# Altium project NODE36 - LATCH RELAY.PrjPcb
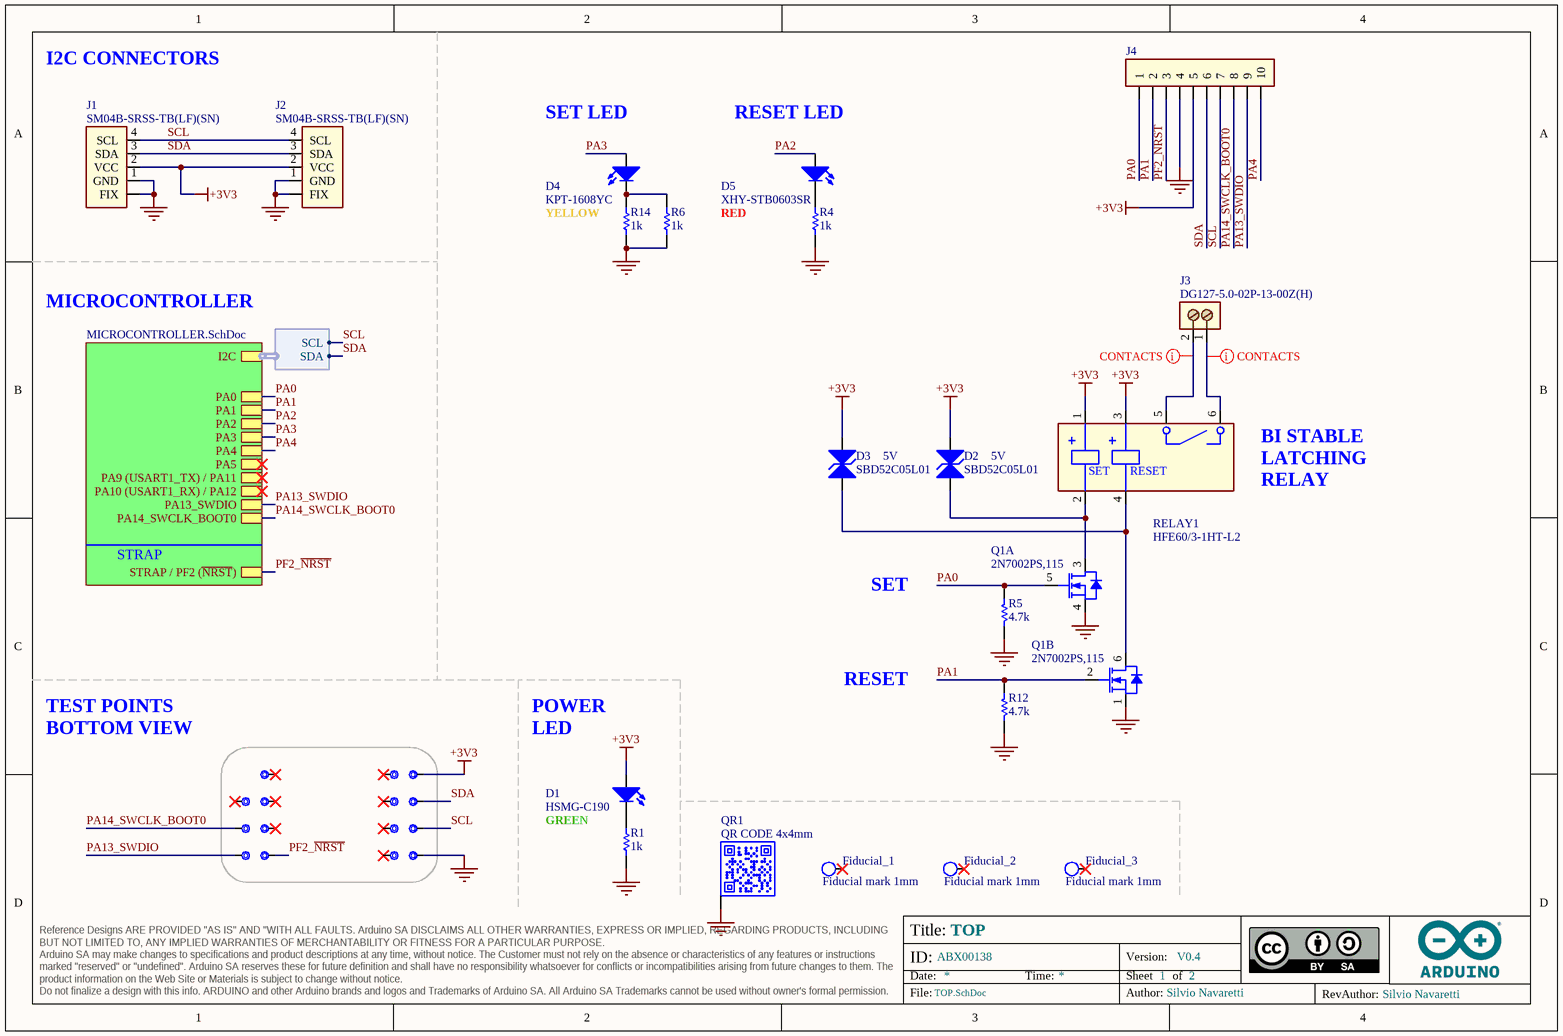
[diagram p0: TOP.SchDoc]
ASSEMBLY_BGA: _; ASSEMBLY_PRESSFIT: _; ASSEMBLY_SMD: X; ASSEMBLY_THT: _; BOARD_CODENAME: NODE36 LATCH RELAY; BOARD_INFO_AUTHOR: Silvio Navaretti; BOARD_INFO_AUTHOR_REV: Silvio Navaretti; BOARD_INFO_Er: _; BOARD_INFO_FLEX: _; BOARD_INFO_FR4: X; BOARD_INFO_FR4_HTG: _; BOARD_INFO_IPC1: _; BOARD_INFO_IPC2: X; BOARD_INFO_IPC3: _; BOARD_INFO_IPC_NA: _; BOARD_INFO_NUMBER_OF_LAYERS: 2; BOARD_INFO_PCB_SIZE: 41.00x25.36mm; BOARD_INFO_POLYMIDE: _; BOARD_INFO_RIGID: X; BOARD_INFO_RIGID/FLEX: _; BOARD_INFO_TBD: _; BOARD_INFO_THICKNESS: 1.6mm; DRILLS_BLIND: _; DRILLS_BURIED: _; DRILLS_COPPER_FILLING: _; DRILLS_FULL: X; DRILLS_LASER: _; DRILLS_PRESSFIT: _; DRILLS_RESIN_FILLING: _; DRILLS_SLOT: _; DRILLS_SOLDER_FILLING: X; FINISH_ADJUSTMENTS: _; FINISH_EDGE_PLATING: _; FINISH_ENIG: _; FINISH_HAL: _; FINISH_HAL_LF: X; FINISH_NI/AU: _; FINISH_SILK_BOTTOM: X; FINISH_SILK_COLOR: WHITE; FINISH_SILK_TOP: X; FINISH_SN/PB: _; FINISH_SOLDERMASK_BOTTOM: X; FINISH_SOLDERMASK_COLOR: BLUE; FINISH_SOLDERMASK_PEELABLE_BOTTOM: _; FINISH_SOLDERMASK_PEELABLE_COLOR: _; FINISH_SOLDERMASK_PEELABLE_TOP: _; FINISH_SOLDERMASK_TOP: X; FINISH_TABS: _; FINISH_TBD: _; INSULATION_MIN_INNER: 0.15mm; INSULATION_MIN_OUTER: 0.15mm; PANEL_MILLING: X; PANEL_NOT_REQUESTED: _; PANEL_NUMBER_OF_FIGURES: 30; PANEL_PROVIDED: X; PANEL_REQUESTED: _; PANEL_SCORING: X; PANEL_SIZE: 262.00x221.00mm; PANEL_TABS: _; SKU: ABX00138; TRACK_MIN_WIDTH_INNER: 0.15mm; TRACK_MIN_WIDTH_OUTER: 0.15mm; Version: V0.4; VIA_1: _; VIA_1_HOLE_MM: _; VIA_1_PAD_MM: _; VIA_2: _; VIA_2_HOLE_MM: _; VIA_2_PAD_MM: _; VIA_3: _; VIA_3_HOLE_MM: _; VIA_3_PAD_MM: _; VIA_4: _; VIA_4_HOLE_MM: _; VIA_4_PAD_MM: _; VIA_5: _; VIA_5_HOLE_MM: _; VIA_5_PAD_MM: _; VIA_THROUGH: X; VIA_THROUGH_HOLE_MM: 0.3; VIA_THROUGH_PAD_MM: 0.6
2 sheets, 43 parts. Net scope: hierarchical (ports join the sheet entries above them; power ports are global).
Board files: PCB.PcbDoc, PANEL.PcbDoc
Sheets:
  TOP.SchDoc
    U_MICROCONTROLLER = MICROCONTROLLER.SchDoc

## Sheet TOP.SchDoc: TOP
size A4; Revision: V0.4; SheetNumber: 1; SheetTotal: 2

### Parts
3V3  Test point 1.00mm  [TP-1.00MM]  (value not drawn)  (no BOM)
D1  HSMG-C190  [LEDC1608X80N-AK]
D2  SBD52C05L01  Voltage Rating (DC): 5V  [SOD523 NO POLARITY]
D3  SBD52C05L01  Voltage Rating (DC): 5V  [SOD523 NO POLARITY]
D4  KPT-1608YC  [LEDC1608X80N-AK]
D5  XHY-STB0603SR  [LEDC1608X80N-AK]
Fiducial_1  Fiducial mark 1mm  [Fiducial mark 1mm-Footprint-1]  (no BOM)
Fiducial_2  Fiducial mark 1mm  [Fiducial mark 1mm-Footprint-1]  (no BOM)
Fiducial_3  Fiducial mark 1mm  [Fiducial mark 1mm-Footprint-1]  (no BOM)
GND  Test point 1.00mm  [TP-1.00MM]  (value not drawn)  (no BOM)
J1  SM04B-SRSS-TB(LF)(SN)  [SM04B-SRSS-TB(LF)(SN)-Footprint-1]
J2  SM04B-SRSS-TB(LF)(SN)  [SM04B-SRSS-TB(LF)(SN)-Footprint-1]
J3  DG127-5.0-02P-13-00Z(H)  [DG127-5.0-02P-14-00A(H)]
J4  HEADER TH 2.54mm VERT. 1x010POS  [PIN HEADER 2.54mm VERT. 1x10POS]  (value not drawn)  (no BOM)
NRST  Test point 1.00mm  [TP-1.00MM]  (value not drawn)  (no BOM)
PA6  Test point 1.00mm  [TP-1.00MM]  (value not drawn)  (no BOM)
PA7  Test point 1.00mm  [TP-1.00MM]  (value not drawn)  (no BOM)
PC14  Test point 1.00mm  [TP-1.00MM]  (value not drawn)  (no BOM)
PC15  Test point 1.00mm  [TP-1.00MM]  (value not drawn)  (no BOM)
Q1  2N7002PS,115  [SOT363]  (parts A,B of 2)
QR1  QR CODE 4x4mm  [QR CODE 4x4mm]  (no BOM)
R1  value 1k  [RES-0402]  (hidden comment: CRCW04021K00FKEDC)
R4  value 1k  [RES-0402]  (hidden comment: CRCW04021K00FKEDC)
R5  value 4.7k  [RES-0402]  (hidden comment: RC0402FR-074K7L)
R6  value 1k  [RES-0402]  (hidden comment: CRCW04021K00FKEDC)
R12  value 4.7k  [RES-0402]  (hidden comment: RC0402FR-074K7L)
R14  value 1k  [RES-0402]  (hidden comment: CRCW04021K00FKEDC)
RELAY1  HFE60/3-1HT-L2  [HFE60/3-1HT-L2]
SCL  Test point 1.00mm  [TP-1.00MM]  (value not drawn)  (no BOM)
SDA  Test point 1.00mm  [TP-1.00MM]  (value not drawn)  (no BOM)
SWCLK  Test point 1.00mm  [TP-1.00MM]  (value not drawn)  (no BOM)
SWDIO  Test point 1.00mm  [TP-1.00MM]  (value not drawn)  (no BOM)
TP9  Test point 1.00mm  [TP-1.00MM]  (value not drawn)  (no BOM)
TP10  Test point 1.00mm  [TP-1.00MM]  (value not drawn)  (no BOM)
TP11  Test point 1.00mm  [TP-1.00MM]  (value not drawn)  (no BOM)
TP12  Test point 1.00mm  [TP-1.00MM]  (value not drawn)  (no BOM)

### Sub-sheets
U_MICROCONTROLLER = MICROCONTROLLER.SchDoc: I2C (harness I2C), PA0, PA1, PA2, PA3, PA4, PA5, PA13_SWDIO, PA14_SWCLK_BOOT0, PA9 (USART1_TX) / PA11, PA10 (USART1_RX) / PA12, STRAP / PF2 (~{NRST})

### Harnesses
I2C: SDA, SCL

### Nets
+3V3: 3V3.X D1.A D2.2(A2) D3.2(A2) J1.2(VCC) J2.2(VCC) J4.5 RELAY1.1 RELAY1.3
GND: GND.X J1.1(GND) J1.FIX J2.1(GND) J2.FIX J4.4 Q1.1(S) Q1.4(S) QR1.PAD R1.1 R4.1 R5.2 R6.1 R12.2 R14.1
PA0: J4.1 Q1.5(G) R5.1 ; sheet U_MICROCONTROLLER/PA0
PA1: J4.2 Q1.2(G) R12.1 ; sheet U_MICROCONTROLLER/PA1
PA2: D5.A ; sheet U_MICROCONTROLLER/PA2
PA3: D4.A ; sheet U_MICROCONTROLLER/PA3
PA4: J4.10 ; sheet U_MICROCONTROLLER/PA4
PA13_SWDIO: J4.9 SWCLK.X ; sheet U_MICROCONTROLLER/PA13_SWDIO
PA14_SWCLK_BOOT0: J4.8 SWDIO.X ; sheet U_MICROCONTROLLER/PA14_SWCLK_BOOT0
PF2_~{NRST}: J4.3 NRST.X ; sheet U_MICROCONTROLLER/STRAP / PF2 (~{NRST})
SCL: J1.4(SCL) J2.4(SCL) J4.7 SCL.X ; sheet U_MICROCONTROLLER/I2C.SCL
SDA: J1.3(SDA) J2.3(SDA) J4.6 SDA.X ; sheet U_MICROCONTROLLER/I2C.SDA
NetD1_C: D1.C R1.2
NetD2_1: D2.1(A1) Q1.3(D) RELAY1.2
NetD3_1: D3.1(A1) Q1.6(D) RELAY1.4
NetD4_C: D4.C R6.2 R14.2
NetD5_C: D5.C R4.2
NetJ3_1: J3.1 RELAY1.6
NetJ3_2: J3.2 RELAY1.5

Not connected (* = marked no-connect by the designer): Fiducial_1 1*; Fiducial_2 1*; Fiducial_3 1*; PA6 X*; PA7 X*; PC14 X*; PC15 X*; TP9 X*; TP10 X*; TP11 X*; TP12 X*

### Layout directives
net class CONTACTS: NetJ3_1, NetJ3_2

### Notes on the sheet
- I2C CONNECTORS
- (near D4) SET LED
- (near D5) RESET LED
- YELLOW
- RED
- MICROCONTROLLER
- (near RELAY1) BI STABLE LATCHING RELAY
- STRAP
- SET
- RESET
- TEST POINTS BOTTOM VIEW
- (near D1) POWER LED
- GREEN

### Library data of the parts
3V3 GND NRST PA6 PA7 PC14 PC15 SCL SDA SWCLK SWDIO TP9-TP12 = UT0013-A.6: Manufacturer: This is not a component
D1 = L0009-A.5: LED SMD 0603 GREEN/568 15mcd 120^; Manufacturer: Broadcom; Code Arduino: 2204
D2 D3 = D0084-A.2: TVS BIDIRECTIONAL SMD Vr 5V, Vbr min 5.6V, 150W, SOD523; Manufacturer: YAGEO; Code Arduino: D0084
D4 = L0008-A.5: LED SMD 0603 GIA588   8mcd 120^; Manufacturer: Kingbright; Code Arduino: 2243
D5 = L0024-A.4: LED SMD 0603 RED 625nm, water clear, 42 to 88 mcd, 120 degrees, 1.6x0.8x0.6mm; Manufacturer: Shenzen Corehy Technology; Code Arduino: L0024
Fiducial_1-Fiducial_3 = UT0023-A.7: Fiducial mark 1mm clearance 2mm
J1 J2 = J0005-A.2: CONN JST 4POS SIDE 1MM TIN QWIIC; Code Arduino: J0005
J3 = J0519-A.6: CONN SCREW TERMINAL 2 POS pitch 5mm height 13.6mm BLACK; Manufacturer: Degson; Code Arduino: J0519
J4 = J0169-A.9: Code Arduino: J0169
Q1 = T0011-A.11: MOSFET 2N-CH 60V 0.32A SOT363; Manufacturer: Nexperia; Device Type: Mosfet 2N-CH SMD; Code Arduino: A5500
QR1 = QR-0001-A.5: QR CODE 4x4mm on layer 34 (This is not a component); Code Arduino: QRCODE_4x4mm
R1 R4 R6 R14 = R0007-A.24: RES CHIP 0402 1k 1% 1/16W; Manufacturer: Vishay; Code Arduino: 0140; Power: 62.5mW; Temperature coefficient: 100ppm
R5 R12 = R0013-A.24: RES CHIP 0402 4k7 1% 1/16W; Manufacturer: YAGEO; Power: 62.5mW; Code Arduino: 2196; Temperature coefficient: 200ppm
RELAY1 = S0067-A.7: Relay Bistable Latching Relay, SPST, 250VAC 5A (cos phi 1) 1250VA, 30VDC 5A 150W, Dual coil 30R 3V, 20.2x11.3x10.5mm; Manufacturer: Hongfa Relay; Code Arduino: S0067

## Sheet MICROCONTROLLER.SchDoc: MICROCONTROLLER
size A4; SheetNumber: 2; SheetTotal: 2
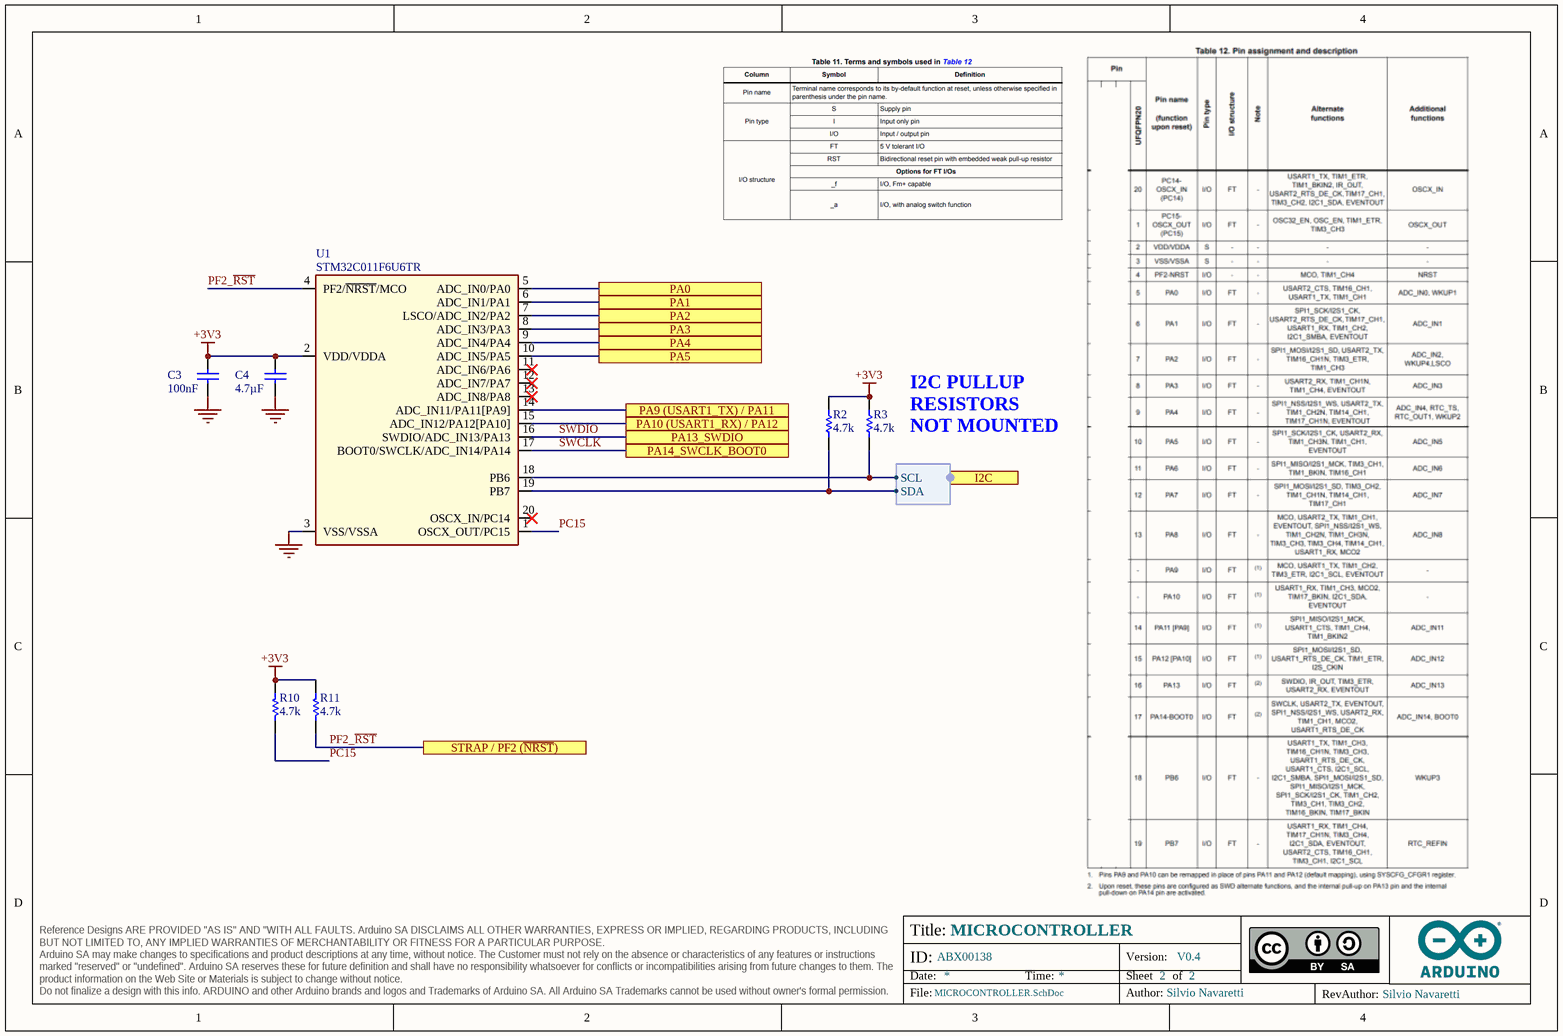
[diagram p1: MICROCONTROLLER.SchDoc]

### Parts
C3  value 100nF  [CAP-0402]  (hidden comment: 0402B104K160CT)
C4  value 4.7µF  [CAP-0603]  (hidden comment: GRM188R61C475KAAJD)
R2  value 4.7k  [RES-0402]  (hidden comment: RC0402FR-074K7L)
R3  value 4.7k  [RES-0402]  (hidden comment: RC0402FR-074K7L)
R10  value 4.7k  [RES-0402]  (hidden comment: RC0402FR-074K7L)
R11  value 4.7k  [RES-0402]  (hidden comment: RC0402FR-074K7L)
U1  STM32C011F6U6TR  [UFQFPN20]

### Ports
I2C (harness I2C), PA0, PA1, PA2, PA3, PA4, PA5, PA9 (USART1_TX) / PA11, PA10 (USART1_RX) / PA12, PA13_SWDIO, PA14_SWCLK_BOOT0, STRAP / PF2 (~{NRST})

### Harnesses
I2C: SDA, SCL

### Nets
+3V3: C3.1 C4.2 R2.2 R3.2 R10.1 R11.1 U1.2(VDD/VDDA)
GND: C3.2 C4.1 U1.3(VSS/VSSA)
PA0: U1.5(ADC_IN0/PA0) ; port PA0
PA1: U1.6(ADC_IN1/PA1) ; port PA1
PA2: U1.7(LSCO/ADC_IN2/PA2) ; port PA2
PA3: U1.8(ADC_IN3/PA3) ; port PA3
PA4: U1.9(ADC_IN4/PA4) ; port PA4
PC15: R10.2 U1.1(OSCX_OUT/PC15)  [project net PC15_2]
PF2_~{RST}: R11.2 U1.4(PF2/~{NRST}/MCO) ; port STRAP / PF2 (~{NRST})  [project net PF2_~{NRST}]
SCL: R3.1 U1.18(PB6) ; port I2C.SCL
SDA: R2.1 U1.19(PB7) ; port I2C.SDA
SWCLK: U1.17(BOOT0/SWCLK/ADC_IN14/PA14) ; port PA14_SWCLK_BOOT0  [project net PA14_SWCLK_BOOT0]
SWDIO: U1.16(SWDIO/ADC_IN13/PA13) ; port PA13_SWDIO  [project net PA13_SWDIO]
NetU1_10: U1.10(ADC_IN5/PA5) ; port PA5
NetU1_14: U1.14(ADC_IN11/PA11[PA9]) ; port PA9 (USART1_TX) / PA11
NetU1_15: U1.15(ADC_IN12/PA12[PA10]) ; port PA10 (USART1_RX) / PA12

Not connected (* = marked no-connect by the designer): U1 11(ADC_IN6/PA6)* 12(ADC_IN7/PA7)* 13(ADC_IN8/PA8)* 20(OSCX_IN/PC14)*

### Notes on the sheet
- (near R3) I2C PULLUP RESISTORS NOT MOUNTED

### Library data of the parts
C3 = C0012-A.15: CAP CHIP 0402 100nF 10% 16V X7R; Manufacturer: Walsin; Code Arduino: 0132
C4 = C0054-A.16: CAP CHIP 0603 4.7uF 10% 16V X5R; Manufacturer: Murata; Code Arduino: A5072
R2 R3 = R0013-A.24: RES CHIP 0402 4k7 1% 1/16W; Manufacturer: YAGEO; Code Arduino: 2196; Power: 62.5mW; Temperature coefficient: 200ppm
R10 R11 = R0013-A.24: as R5 on sheet TOP
U1 = U0390-A.1: IC Cortex M0, 32b MCU, 32KB Flash, 6KB RAM, VDD 2-3.6V, -40°C to 85°C, QFN20 3x3mm; Manufacturer: ST Microelectronics; Code Arduino: U0390

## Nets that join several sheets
+3V3: TOP (9 pins), MICROCONTROLLER (7 pins)
GND: TOP (15 pins), MICROCONTROLLER (C3.2 C4.1 U1.3)
PA0: TOP (J4.1 Q1.5 R5.1), MICROCONTROLLER (U1.5)
PA1: TOP (J4.2 Q1.2 R12.1), MICROCONTROLLER (U1.6)
PA2: TOP (D5.A), MICROCONTROLLER (U1.7)
PA3: TOP (D4.A), MICROCONTROLLER (U1.8)
PA4: TOP (J4.10), MICROCONTROLLER (U1.9)
PA13_SWDIO: TOP (J4.9 SWCLK.X), MICROCONTROLLER (U1.16)
PA14_SWCLK_BOOT0: TOP (J4.8 SWDIO.X), MICROCONTROLLER (U1.17)
PF2_~{NRST}: TOP (J4.3 NRST.X), MICROCONTROLLER (R11.2 U1.4)
SCL: TOP (J1.4 J2.4 J4.7 SCL.X), MICROCONTROLLER (R3.1 U1.18)
SDA: TOP (J1.3 J2.3 J4.6 SDA.X), MICROCONTROLLER (R2.1 U1.19)

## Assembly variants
ABX00138: not fitted R2 R3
